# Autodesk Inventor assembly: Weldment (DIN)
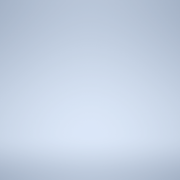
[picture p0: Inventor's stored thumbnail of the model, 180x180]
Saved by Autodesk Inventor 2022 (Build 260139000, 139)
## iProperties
Created: 2021-02
Part Number: Weldment (DIN)
Document SubType Name: Weldment
Weld Material: Welded Aluminum-6061
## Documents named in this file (1)
- C:\Users\ENU\Desktop\New folder for ita\Weldment (DIN).iam
